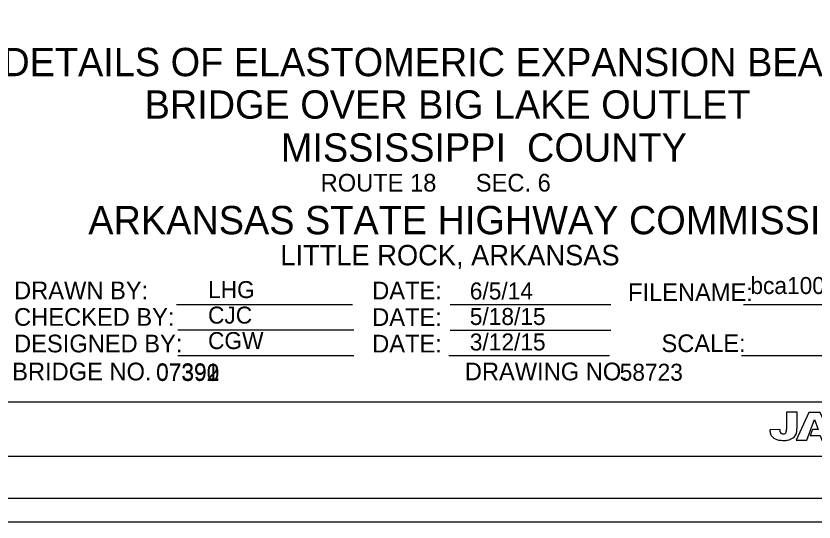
# Model space of a CAD drawing. Extents: x -194 to 226, y 505 to 725.
# Drawn here: x 76.6 to 132.9, y 505.4 to 541.1 of the extents above; entities that cross this region are included whole.
import ezdxf

# ---------------------------------------------------------------- set-up
doc = ezdxf.new("R2010")
doc.units = 0
for name, color, linetype in [('border', 7, 'Continuous'), ('Border 2660-Hwy18 - Level 62', 7, 'Continuous'), ('Border 2660-Hwy18 - Level 63', 7, 'Continuous'), ('Border 2660-Hwy18 - Text', 7, 'Continuous'), ('Border 2660-Hwy18 - Title Text', 7, 'Continuous'), ('Bridge No BLFR', 7, 'Continuous'), ('Bridge No BLO', 7, 'Continuous'), ('Bridge No Ditch 81', 7, 'Continuous'), ('Level 62 PDF', 7, 'Continuous'), ('Text', 7, 'Continuous'), ('Title Block Text', 7, 'Continuous'), ('Title Text', 7, 'Continuous')]:
    doc.layers.add(name, color=color, linetype=linetype)

msp = doc.modelspace()

# ---------------------------------------------------------------- linework, layer by layer
at = {"layer": 'border'}
for p, q in [((87.907, 520.772), (100.339, 520.772)), ((107.239, 520.76), (118.579, 520.76)), ((127.939, 520.76), (141.3, 520.76)), ((87.979, 518.972), (100.411, 518.972)), ((107.239, 518.96), (118.579, 518.96)), ((87.979, 517.172), (100.411, 517.172)), ((107.131, 517.16), (118.471, 517.16)), ((127.815, 517.16), (139.471, 517.16)), ((143.779, 513.86), (-176.332, 513.86))]:
    msp.add_line(p, q, dxfattribs=at)
for points in [[(131.728, 512.064), (131.728, 513.165), (130.987, 513.165), (130.987, 511.958)], [(132.956, 512.638), (133.216, 511.934), (132.829, 511.934), (132.668, 511.51), (133.37, 511.51), (133.488, 511.186), (134.263, 511.186), (133.367, 513.147), (132.56, 513.147), (131.661, 511.186), (132.417, 511.186), (132.956, 512.638)], [(130.512, 511.949), (129.804, 511.912)]]:
    msp.add_lwpolyline(points, dxfattribs=at)
for centre, radius, start, end in [((131.024, 512.008), 1.226, 184.5698, 198.1069), ((131.115, 511.928), 0.602, 178.2556, 191.4961), ((130.195, 511.955), 0.792, 349.1575, 360), ((130.492, 512.023), 1.237, 351.3706, 1.8291), ((130.359, 511.791), 0.527, 198.1069, 225.9799), ((130.547, 511.985), 0.797, 225.9799, 261.0714), ((130.796, 511.863), 0.277, 191.4961, 218.7511), ((130.708, 511.793), 0.164, 218.7511, 257.488), ((130.747, 511.97), 0.345, 257.488, 275.7834), ((130.756, 511.882), 0.257, 275.7834, 301.6926), ((130.827, 511.768), 0.122, 301.6926, 325.4171), ((130.693, 511.86), 0.285, 325.4171, 349.1575), ((130.919, 512.109), 0.931, 279.1616, 305.8646), ((131.122, 511.829), 0.585, 305.8646, 338.7843), ((131.175, 511.808), 0.527, 338.7843, 350.0951), ((126.285, 512.662), 5.492, 350.0951, 351.3706), ((130.802, 513.61), 2.441, 261.0714, 269.9405), ((130.801, 512.839), 1.671, 269.9405, 279.1616)]:
    msp.add_arc(centre, radius, start, end, dxfattribs=at)
at = {"layer": 'Border 2660-Hwy18 - Level 62'}
msp.add_lwpolyline([(-192.533, 725.169), (148.651, 725.169), (148.651, 507.073), (-192.533, 507.073)], close=True, dxfattribs=at)
at = {"layer": 'Border 2660-Hwy18 - Level 63'}
msp.add_lwpolyline([(-193.644, 723.74), (146.351, 723.74), (146.351, 510.044), (-193.644, 510.044)], close=True, dxfattribs=at)
at = {"layer": 'Level 62 PDF'}
msp.add_lwpolyline([(-190.033, 723.503), (151.151, 723.503), (151.151, 505.407), (-190.033, 505.407)], close=True, dxfattribs=at)

# ---------------------------------------------------------------- texts
at = {"layer": 'Border 2660-Hwy18 - Text'}
for s, p in [('DRAWN BY:', (76.423, 521.137)), ('DATE:', (101.719, 521.127)), ('FILENAME:', (119.789, 521.005)), ('CHECKED BY:', (76.423, 519.262)), ('DATE:', (101.719, 519.252)), ('DESIGNED BY:', (76.423, 517.387)), ('SCALE:', (122.155, 517.405)), ('DATE:', (101.719, 517.377)), ('BRIDGE NO.', (76.288, 515.41)), ('DRAWING NO.', (108.262, 515.412))]:
    msp.add_text(s, height=1.25, dxfattribs=at).set_placement(p)
at = {"layer": 'Border 2660-Hwy18 - Title Text'}
for s, height, p in [('MISSISSIPPI  COUNTY', 1.99999, (95.269, 530.85)), ('ROUTE 18      SEC. 6', 1.25, (98.078, 528.739)), ('ARKANSAS STATE HIGHWAY COMMISSION', 1.99999, (81.666, 525.724)), ('LITTLE ROCK, ARKANSAS', 1.44, (95.227, 523.532))]:
    msp.add_text(s, height=height, dxfattribs=at).set_placement(p)
at = {"layer": 'Bridge No BLFR'}
msp.add_text('07392', height=1.2, dxfattribs=at).set_placement((86.457, 515.366))
at = {"layer": 'Bridge No BLO'}
msp.add_text('07391', height=1.2, dxfattribs=at).set_placement((86.457, 515.411))
at = {"layer": 'Bridge No Ditch 81'}
msp.add_text('07390', height=1.2, dxfattribs=at).set_placement((86.457, 515.366))
at = {"layer": 'Text'}
for s, p in [('LHG', (90.122, 521.217)), ('6/5/14', (108.614, 521.119)), ('CJC', (90.122, 519.417)), ('5/18/15', (108.614, 519.319)), ('CGW', (90.122, 517.617)), ('3/12/15', (108.614, 517.519))]:
    msp.add_text(s, height=1.2, dxfattribs=at).set_placement(p)
at = {"layer": 'Title Block Text'}
for s, p in [('bca1002x2_ex1.dgn', (128.434, 521.505)), ('58723', (119.203, 515.384))]:
    msp.add_text(s, height=1.2, dxfattribs=at).set_placement(p)
at = {"layer": 'Title Text'}
for s, p in [('DETAILS OF ELASTOMERIC EXPANSION BEARINGS ', (75.593, 536.885)), ('BRIDGE OVER BIG LAKE OUTLET', (85.645, 533.885))]:
    msp.add_text(s, height=1.99999, dxfattribs=at).set_placement(p)

doc.saveas('drawing.dxf')
